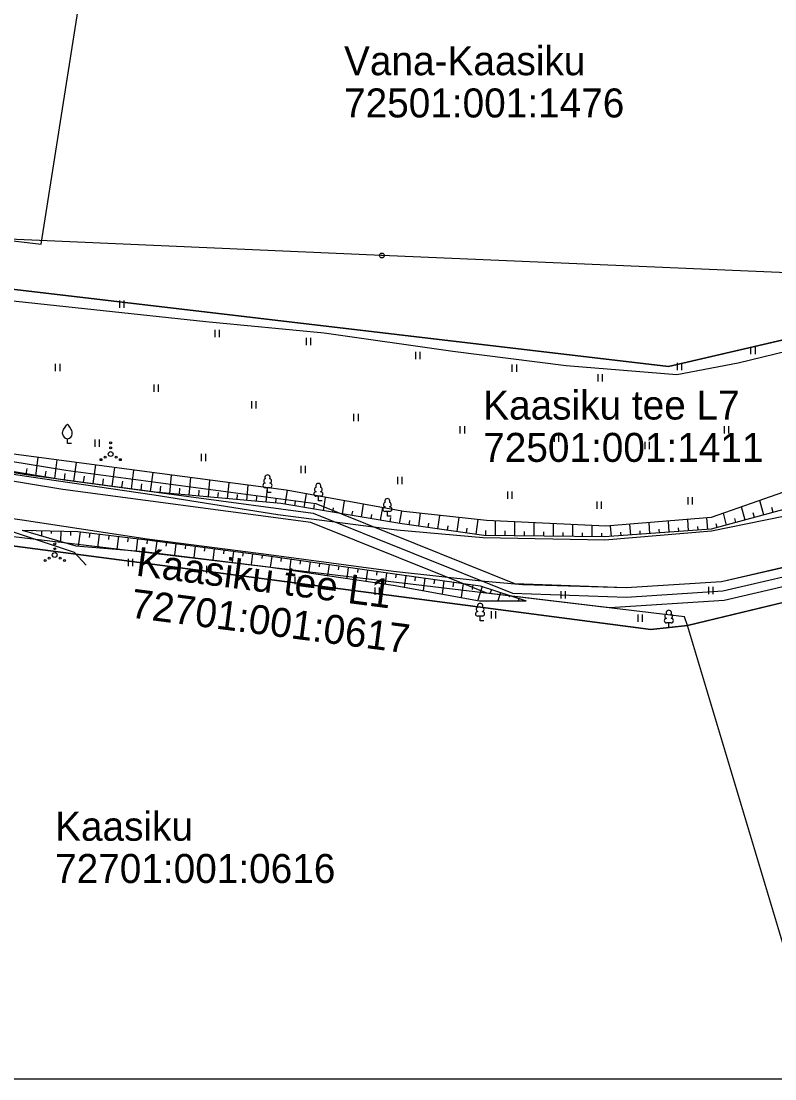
# Model space of a CAD drawing. Extents: x 532656 to 533339, y 6581345 to 6581629.
# Drawn here: x 533058.1 to 533136.1, y 6581421.7 to 6581531.1 of the extents above; entities that cross this region are included whole.
import ezdxf

# ---------------------------------------------------------------- set-up
doc = ezdxf.new("R2010")
doc.units = 0
for name, color, linetype in [('HALJASTUS', 7, 'Continuous'), ('KASUTUSALA', 7, 'Continuous'), ('MPKAABEL', 7, 'Continuous'), ('MPOHULIIN', 7, 'Continuous'), ('PIIR', 7, 'Continuous'), ('POST', 7, 'Continuous'), ('PR_SIDE', 7, 'Continuous'), ('PUU', 7, 'Continuous'), ('RELJEEF', 7, 'Continuous'), ('TEE', 7, 'Continuous'), ('VORMISTUS', 7, 'Continuous')]:
    doc.layers.add(name, color=color, linetype=linetype)

msp = doc.modelspace()

# ---------------------------------------------------------------- linework, layer by layer
at = {"layer": 'HALJASTUS'}
for p, q in [((533068.28, 6581502.21), (533068.28, 6581501.45)), ((533068.73, 6581502.21), (533068.73, 6581501.45)), ((533078.15, 6581499.17), (533078.15, 6581498.41)), ((533078.61, 6581499.17), (533078.61, 6581498.41)), ((533087.6, 6581498.33), (533087.6, 6581497.57)), ((533088.06, 6581498.33), (533088.06, 6581497.57)), ((533133.6, 6581497.4), (533133.6, 6581496.64)), ((533134.06, 6581497.4), (533134.06, 6581496.64)), ((533098.91, 6581496.89), (533098.91, 6581496.13)), ((533099.37, 6581496.89), (533099.37, 6581496.13)), ((533061.65, 6581495.63), (533061.65, 6581494.87)), ((533062.11, 6581495.63), (533062.11, 6581494.87)), ((533108.91, 6581495.58), (533108.91, 6581494.82)), ((533109.37, 6581495.58), (533109.37, 6581494.82)), ((533126.01, 6581495.75), (533126.01, 6581494.99)), ((533126.46, 6581495.75), (533126.46, 6581494.99)), ((533117.78, 6581494.57), (533117.78, 6581493.81)), ((533118.23, 6581494.57), (533118.23, 6581493.81)), ((533071.84, 6581493.49), (533071.84, 6581492.73)), ((533072.3, 6581493.49), (533072.3, 6581492.73)), ((533081.96, 6581491.79), (533081.96, 6581491.03)), ((533082.41, 6581491.79), (533082.41, 6581491.03)), ((533092.52, 6581490.46), (533092.52, 6581489.7)), ((533092.98, 6581490.46), (533092.98, 6581489.7)), ((533103.52, 6581489.21), (533103.52, 6581488.44)), ((533103.98, 6581489.21), (533103.98, 6581488.44)), ((533130.85, 6581489.21), (533130.85, 6581488.44)), ((533131.3, 6581489.21), (533131.3, 6581488.44)), ((533065.74, 6581487.83), (533065.74, 6581487.07)), ((533066.2, 6581487.83), (533066.2, 6581487.07)), ((533113.27, 6581488.32), (533113.27, 6581487.56)), ((533113.73, 6581488.32), (533113.73, 6581487.56)), ((533122.65, 6581487.58), (533122.65, 6581486.82)), ((533123.11, 6581487.58), (533123.11, 6581486.82)), ((533076.76, 6581486.35), (533076.76, 6581485.59)), ((533077.21, 6581486.35), (533077.21, 6581485.59)), ((533087.06, 6581485.09), (533087.06, 6581484.33)), ((533087.51, 6581485.09), (533087.51, 6581484.33)), ((533097.06, 6581483.95), (533097.06, 6581483.19)), ((533097.51, 6581483.95), (533097.51, 6581483.19)), ((533108.45, 6581482.43), (533108.45, 6581481.67)), ((533108.91, 6581482.43), (533108.91, 6581481.67)), ((533117.69, 6581481.41), (533117.69, 6581480.65)), ((533118.15, 6581481.41), (533118.15, 6581480.65)), ((533127.1, 6581481.84), (533127.1, 6581481.08)), ((533127.56, 6581481.84), (533127.56, 6581481.08)), ((533069.19, 6581475.46), (533069.19, 6581474.7)), ((533069.64, 6581475.46), (533069.64, 6581474.7)), ((533077.29, 6581474.74), (533077.29, 6581473.98)), ((533077.75, 6581474.74), (533077.75, 6581473.98)), ((533086.45, 6581473.6), (533086.45, 6581472.84)), ((533086.9, 6581473.6), (533086.9, 6581472.84)), ((533094.72, 6581472.5), (533094.72, 6581471.74)), ((533095.18, 6581472.5), (533095.18, 6581471.74)), ((533129.24, 6581472.59), (533129.24, 6581471.82)), ((533129.69, 6581472.59), (533129.69, 6581471.82)), ((533113.96, 6581472.12), (533113.96, 6581471.36)), ((533114.42, 6581472.12), (533114.42, 6581471.36)), ((533106.75, 6581470.05), (533106.75, 6581469.29)), ((533107.2, 6581470.05), (533107.2, 6581469.29)), ((533121.94, 6581469.71), (533121.94, 6581468.95)), ((533122.39, 6581469.71), (533122.39, 6581468.95))]:
    msp.add_line(p, q, dxfattribs=at)
msp.add_lwpolyline([(533032.97, 6581478.99), (533033.72, 6581480.95), (533045.3, 6581480.01), (533057.4, 6581478.22), (533063.59, 6581476.17), (533064.85, 6581474.81)], dxfattribs=at)
for centre, radius in [((533067.38, 6581487.46), 0.1), ((533067.38, 6581486.31), 0.25), ((533067.38, 6581486.96), 0.1), ((533066.38, 6581485.73), 0.1), ((533066.82, 6581485.98), 0.1), ((533067.95, 6581485.98), 0.1), ((533068.38, 6581485.73), 0.1), ((533061.59, 6581477.02), 0.1), ((533061.59, 6581476.52), 0.1), ((533061.02, 6581475.54), 0.1), ((533061.59, 6581475.87), 0.25), ((533062.15, 6581475.54), 0.1), ((533060.59, 6581475.29), 0.1), ((533062.59, 6581475.29), 0.1)]:
    msp.add_circle(centre, radius, dxfattribs=at)
at = {"layer": 'KASUTUSALA'}
for points in [[(533013.98, 6581493.3), (533015.9, 6581507.09), (533016.05, 6581508.19), (533018.04, 6581507.96), (533017.92, 6581507.09), (533016.06, 6581493.72), (533016.82, 6581492.43), (533018.77, 6581491.63), (533020.53, 6581491.21), (533026.48, 6581490.1), (533037.85, 6581488.72), (533062.74, 6581484.63), (533088.6, 6581481.18), (533109.16, 6581472.91), (533120.73, 6581472.5), (533130.59, 6581473.14), (533152.46, 6581478.24)], [(533152.98, 6581476.31), (533130.88, 6581471.16), (533119.05, 6581470.39), (533116.99, 6581470.63), (533106.31, 6581471.91), (533088.09, 6581479.24), (533062.44, 6581482.66), (533037.57, 6581486.74), (533026.18, 6581488.12), (533021.07, 6581489.07), (533020.13, 6581489.24), (533009.66, 6581490.74)]]:
    msp.add_lwpolyline(points, dxfattribs=at)
at = {"layer": 'MPKAABEL'}
msp.add_lwpolyline([(533187.88, 6581502.84), (533186.34, 6581502.82), (533179.65, 6581502.93), (533170.99, 6581502.81), (533161.86, 6581502.74), (533157.45, 6581501.85), (533146.33, 6581499.15), (533143.65, 6581498.48), (533132.32, 6581495.71), (533125.95, 6581494.5), (533114.52, 6581495.45), (533102.79, 6581496.92), (533089.47, 6581498.82), (533077.24, 6581500), (533065.63, 6581501.23), (533053.69, 6581502.51), (533042.29, 6581503.73), (533032.02, 6581504.88), (533032.28, 6581506.42), (533031.89, 6581506.81)], dxfattribs=at)
msp.add_lwpolyline([(533187.88, 6581502.84), (533186.34, 6581502.82), (533179.65, 6581502.93), (533170.99, 6581502.81), (533161.86, 6581502.74), (533157.45, 6581501.85), (533146.33, 6581499.15), (533143.65, 6581498.48), (533132.32, 6581495.71), (533125.95, 6581494.5), (533114.52, 6581495.45), (533102.79, 6581496.92), (533089.47, 6581498.82), (533077.24, 6581500), (533065.63, 6581501.23), (533053.69, 6581502.51), (533042.29, 6581503.73), (533032.02, 6581504.88), (533032.28, 6581506.42), (533031.89, 6581506.81)], dxfattribs=at)
at = {"layer": 'MPOHULIIN'}
msp.add_lwpolyline([(533275.32, 6581502.37), (533268.53, 6581499.28), (533228.29, 6581500.87), (533187.88, 6581502.84), (533141.43, 6581504.88), (533095.45, 6581506.85), (533050.54, 6581508.81), (533010.87, 6581510.54), (532997.7, 6581528.31)], dxfattribs=at)
at = {"layer": 'PIIR'}
for points in [[(532997.7, 6581558.35), (533016.96, 6581555.16), (533011.51, 6581513.79), (533060.19, 6581508.02), (533066.33, 6581546.98), (533091.13, 6581542.87), (533143.65, 6581562.67), (533173.8, 6581529.09), (533205.25, 6581513.98), (533125.12, 6581495.35), (532997.7, 6581510.35)], [(532997.7, 6581510.35), (533125.12, 6581495.35), (533271.76, 6581529.44), (533289.68, 6581507.68), (533127.07, 6581468.59), (533126.77, 6581469.47), (532997.7, 6581484.84)], [(533141.13, 6581421.68), (533127.07, 6581468.59), (533267.77, 6581502.5), (533292.38, 6581484.15), (533309.59, 6581464.94)], [(532997.7, 6581483.86), (533035.33, 6581479.69), (533123.26, 6581468.15), (533127.07, 6581468.59), (533126.77, 6581469.47), (532997.7, 6581484.84)], [(533141.13, 6581421.68), (533127.07, 6581468.59), (533123.26, 6581468.15), (533035.33, 6581479.69), (533032.98, 6581458.23), (533019.26, 6581430.2), (532997.7, 6581433.84)]]:
    msp.add_lwpolyline(points, dxfattribs=at)
msp.add_lwpolyline([(533066.33, 6581546.98), (533016.96, 6581555.16), (533011.51, 6581513.79), (533060.19, 6581508.02)], close=True, dxfattribs=at)
at = {"layer": 'POST'}
for radius in [0.25, 0.0234]:
    msp.add_circle((533095.45, 6581506.85), radius, dxfattribs=at)
at = {"layer": 'PR_SIDE'}
msp.add_lwpolyline([(533009.76, 6581491.73), (533020.32, 6581490.23), (533026.33, 6581489.11), (533037.71, 6581487.73), (533062.59, 6581483.65), (533088.35, 6581480.21), (533108.95, 6581471.92), (533120.75, 6581471.5), (533130.73, 6581472.15), (533152.72, 6581477.27), (533179.95, 6581485.59), (533320.87, 6581524.82)], dxfattribs=at)
at = {"layer": 'PUU'}
for p, q in [((533062.91, 6581487.4), (533062.91, 6581487.9)), ((533063.31, 6581487.4), (533062.91, 6581487.4)), ((533083.86, 6581482.83), (533083.38, 6581482.83)), ((533083.62, 6581482.35), (533083.62, 6581482.83)), ((533084, 6581482.35), (533083.62, 6581482.35)), ((533089.11, 6581481.94), (533088.63, 6581481.94)), ((533088.87, 6581481.47), (533088.87, 6581481.94)), ((533089.25, 6581481.47), (533088.87, 6581481.47)), ((533096.25, 6581480.38), (533095.77, 6581480.38)), ((533096.01, 6581479.9), (533096.01, 6581480.38)), ((533096.39, 6581479.9), (533096.01, 6581479.9)), ((533105.85, 6581469.54), (533105.37, 6581469.54)), ((533105.61, 6581469.07), (533105.61, 6581469.54)), ((533105.99, 6581469.07), (533105.61, 6581469.07)), ((533125.37, 6581468.84), (533124.89, 6581468.84)), ((533125.13, 6581468.36), (533125.13, 6581468.84)), ((533125.51, 6581468.36), (533125.13, 6581468.36))]:
    msp.add_line(p, q, dxfattribs=at)
for points in [[(533062.41, 6581488.4), (533062.41, 6581488.55), (533062.42, 6581488.61), (533062.45, 6581488.74), (533062.51, 6581488.86), (533062.66, 6581489.1), (533062.82, 6581489.3), (533062.91, 6581489.4)], [(533063.41, 6581488.4), (533063.41, 6581488.55), (533063.4, 6581488.61), (533063.36, 6581488.74), (533063.3, 6581488.86), (533063.16, 6581489.1), (533063, 6581489.3), (533062.91, 6581489.4)]]:
    msp.add_lwpolyline(points, dxfattribs=at)
for centre, radius, start, end in [((533062.91, 6581488.4), 0.5, 180, 0), ((533083.38, 6581483.07), 0.238, 90.0016, 269.3953), ((533083.45, 6581483.53), 0.233, 109.0217, 253.1415), ((533083.62, 6581483.87), 0.277, 332.5799, 207.4201), ((533083.79, 6581483.53), 0.233, 286.8508, 70.9859), ((533083.85, 6581483.07), 0.238, 270.6047, 89.9984), ((533088.87, 6581482.99), 0.277, 332.5799, 207.4201), ((533088.63, 6581482.18), 0.238, 90.0016, 269.3953), ((533088.7, 6581482.64), 0.233, 109.0217, 253.1415), ((533089.04, 6581482.64), 0.233, 286.8508, 70.9859), ((533089.1, 6581482.18), 0.238, 270.6047, 89.9984), ((533095.84, 6581481.07), 0.233, 109.0217, 253.1415), ((533096.01, 6581481.42), 0.277, 332.5799, 207.4201), ((533096.18, 6581481.07), 0.233, 286.8508, 70.9859), ((533095.77, 6581480.61), 0.238, 90.0016, 269.3953), ((533096.25, 6581480.61), 0.238, 270.6047, 89.9984), ((533105.37, 6581469.78), 0.238, 90.0016, 269.3953), ((533105.44, 6581470.24), 0.233, 109.0217, 253.1415), ((533105.61, 6581470.59), 0.277, 332.5799, 207.4201), ((533105.78, 6581470.24), 0.233, 286.8508, 70.9859), ((533105.84, 6581469.78), 0.238, 270.6047, 89.9984), ((533125.13, 6581469.88), 0.277, 332.5799, 207.4201), ((533124.9, 6581469.08), 0.238, 90.0016, 269.3953), ((533124.96, 6581469.54), 0.233, 109.0217, 253.1415), ((533125.3, 6581469.54), 0.233, 286.8508, 70.9859), ((533125.37, 6581469.08), 0.238, 270.6047, 89.9984)]:
    msp.add_arc(centre, radius, start, end, dxfattribs=at)
at = {"layer": 'RELJEEF'}
for p, q in [((533059.62, 6581484.05), (533059.88, 6581485.97)), ((533061.6, 6581483.78), (533061.86, 6581485.7)), ((533063.58, 6581483.51), (533063.84, 6581485.44)), ((533058.63, 6581484.19), (533058.73, 6581484.82)), ((533060.61, 6581483.91), (533060.7, 6581484.55)), ((533062.59, 6581483.65), (533062.68, 6581484.29)), ((533065.57, 6581483.25), (533065.83, 6581485.18)), ((533067.55, 6581482.98), (533067.81, 6581484.92)), ((533069.53, 6581482.71), (533069.79, 6581484.66)), ((533071.51, 6581482.45), (533071.77, 6581484.39)), ((533064.57, 6581483.38), (533064.66, 6581484.02)), ((533066.56, 6581483.11), (533066.64, 6581483.76)), ((533068.54, 6581482.85), (533068.63, 6581483.49)), ((533070.52, 6581482.58), (533070.61, 6581483.23)), ((533073.5, 6581482.24), (533073.68, 6581484.14)), ((533075.49, 6581482.06), (533075.66, 6581483.88)), ((533077.49, 6581481.88), (533077.64, 6581483.61)), ((533079.48, 6581481.7), (533079.63, 6581483.35)), ((533072.51, 6581482.34), (533072.57, 6581482.98)), ((533074.5, 6581482.15), (533074.55, 6581482.77)), ((533076.49, 6581481.97), (533076.54, 6581482.56)), ((533078.48, 6581481.79), (533078.53, 6581482.35)), ((533080.47, 6581481.6), (533080.52, 6581482.14)), ((533081.47, 6581481.51), (533081.61, 6581483.08)), ((533083.46, 6581481.33), (533083.6, 6581482.81)), ((533085.45, 6581481.11), (533085.68, 6581482.53)), ((533087.42, 6581480.78), (533087.65, 6581482.18)), ((533082.46, 6581481.42), (533082.51, 6581481.93)), ((533084.46, 6581481.24), (533084.5, 6581481.72)), ((533086.43, 6581480.95), (533086.51, 6581481.42)), ((533088.41, 6581480.62), (533088.48, 6581481.08)), ((533089.39, 6581480.45), (533089.62, 6581481.82)), ((533091.36, 6581480.12), (533091.59, 6581481.47)), ((533093.34, 6581479.79), (533093.56, 6581481.12)), ((533134.97, 6581480), (533134.56, 6581481.52)), ((533090.38, 6581480.29), (533090.45, 6581480.74)), ((533092.35, 6581479.95), (533092.43, 6581480.4)), ((533094.32, 6581479.62), (533094.4, 6581480.06)), ((533095.31, 6581479.46), (533095.53, 6581480.77)), ((533097.28, 6581479.13), (533097.5, 6581480.41)), ((533099.26, 6581478.85), (533099.45, 6581480.18)), ((533101.24, 6581478.57), (533101.44, 6581479.96)), ((533131.11, 6581478.96), (533130.78, 6581480.18)), ((533133.04, 6581479.48), (533132.67, 6581480.85)), ((533134, 6581479.74), (533133.87, 6581480.22)), ((533135.94, 6581480.26), (533135.79, 6581480.79)), ((533096.3, 6581479.29), (533096.37, 6581479.73)), ((533098.27, 6581478.99), (533098.33, 6581479.42)), ((533100.25, 6581478.71), (533100.32, 6581479.16)), ((533102.23, 6581478.43), (533102.3, 6581478.9)), ((533103.22, 6581478.29), (533103.43, 6581479.75)), ((533105.2, 6581478.01), (533105.42, 6581479.53)), ((533107.19, 6581477.88), (533107.21, 6581479.39)), ((533109.19, 6581477.85), (533109.21, 6581479.29)), ((533111.19, 6581477.83), (533111.21, 6581479.2)), ((533113.19, 6581477.8), (533113.21, 6581479.1)), ((533115.19, 6581477.78), (533115.21, 6581479.01)), ((533117.19, 6581477.75), (533117.21, 6581478.92)), ((533119.19, 6581477.78), (533119.11, 6581478.89)), ((533121.19, 6581477.93), (533121.11, 6581479.05)), ((533123.18, 6581478.07), (533123.1, 6581479.22)), ((533125.18, 6581478.22), (533125.09, 6581479.38)), ((533127.17, 6581478.36), (533127.09, 6581479.54)), ((533128.17, 6581478.43), (533128.14, 6581478.83)), ((533129.17, 6581478.5), (533129.08, 6581479.71)), ((533130.14, 6581478.7), (533130.04, 6581479.08)), ((533132.07, 6581479.22), (533131.96, 6581479.65)), ((533059.22, 6581478.42), (533059.22, 6581478.33)), ((533060.22, 6581478.4), (533060.21, 6581477.86)), ((533061.22, 6581478.37), (533061.21, 6581478.1)), ((533062.22, 6581478.35), (533062.19, 6581477.27)), ((533063.22, 6581478.33), (533063.21, 6581477.88)), ((533064.22, 6581478.28), (533064.03, 6581476.78)), ((533065.21, 6581478.16), (533065.15, 6581477.67)), ((533066.2, 6581478.04), (533066.03, 6581476.62)), ((533067.19, 6581477.92), (533067.14, 6581477.46)), ((533068.19, 6581477.8), (533068.02, 6581476.46)), ((533069.18, 6581477.67), (533069.13, 6581477.24)), ((533104.21, 6581478.15), (533104.28, 6581478.64)), ((533106.2, 6581477.89), (533106.2, 6581478.41)), ((533108.19, 6581477.87), (533108.2, 6581478.36)), ((533110.19, 6581477.84), (533110.2, 6581478.31)), ((533112.19, 6581477.81), (533112.2, 6581478.26)), ((533114.19, 6581477.79), (533114.2, 6581478.21)), ((533116.19, 6581477.76), (533116.2, 6581478.16)), ((533118.19, 6581477.74), (533118.2, 6581478.11)), ((533120.19, 6581477.86), (533120.16, 6581478.23)), ((533122.18, 6581478), (533122.16, 6581478.38)), ((533124.18, 6581478.14), (533124.15, 6581478.53)), ((533126.17, 6581478.29), (533126.15, 6581478.68)), ((533070.17, 6581477.55), (533070.02, 6581476.29)), ((533071.17, 6581477.43), (533071.11, 6581477.02)), ((533072.16, 6581477.3), (533072, 6581476.08)), ((533073.15, 6581477.17), (533073.09, 6581476.77)), ((533074.14, 6581477.04), (533073.98, 6581475.84)), ((533075.13, 6581476.91), (533075.08, 6581476.51)), ((533076.12, 6581476.78), (533075.97, 6581475.6)), ((533077.11, 6581476.64), (533077.06, 6581476.25)), ((533078.1, 6581476.51), (533077.95, 6581475.35)), ((533079.1, 6581476.38), (533079.05, 6581476)), ((533080.09, 6581476.25), (533079.94, 6581475.11)), ((533081.08, 6581476.12), (533081.03, 6581475.74)), ((533082.07, 6581475.99), (533081.92, 6581474.87)), ((533083.06, 6581475.86), (533083.01, 6581475.49)), ((533084.05, 6581475.72), (533083.89, 6581474.62)), ((533085.04, 6581475.58), (533084.99, 6581475.21)), ((533086.03, 6581475.44), (533085.87, 6581474.33)), ((533087.02, 6581475.3), (533086.97, 6581474.92)), ((533088.01, 6581475.16), (533087.85, 6581474.03)), ((533089, 6581475.01), (533088.95, 6581474.64)), ((533089.99, 6581474.87), (533089.83, 6581473.74)), ((533090.98, 6581474.73), (533090.93, 6581474.35)), ((533091.97, 6581474.59), (533091.81, 6581473.45)), ((533092.96, 6581474.45), (533092.91, 6581474.07)), ((533093.95, 6581474.31), (533093.79, 6581473.16)), ((533094.94, 6581474.17), (533094.89, 6581473.78)), ((533095.93, 6581474.02), (533095.77, 6581472.87)), ((533096.92, 6581473.88), (533096.87, 6581473.49)), ((533097.91, 6581473.75), (533097.74, 6581472.54)), ((533098.9, 6581473.61), (533098.84, 6581473.19)), ((533099.89, 6581473.47), (533099.71, 6581472.19)), ((533100.88, 6581473.33), (533100.82, 6581472.89)), ((533101.87, 6581473.19), (533101.68, 6581471.84)), ((533102.86, 6581473.05), (533102.8, 6581472.59)), ((533103.85, 6581472.91), (533103.65, 6581471.49)), ((533104.84, 6581472.78), (533104.78, 6581472.29)), ((533105.83, 6581472.6), (533105.37, 6581471.18)), ((533106.78, 6581472.3), (533106.66, 6581471.91)), ((533107.73, 6581471.99), (533107.46, 6581471.14)), ((533108.68, 6581471.69), (533108.63, 6581471.51)), ((533109.64, 6581471.38), (533109.56, 6581471.14))]:
    msp.add_line(p, q, dxfattribs=at)
for points in [[(533281.18, 6581520.42), (533276.05, 6581519.36), (533263.6, 6581516.53), (533251.65, 6581514.59), (533239.04, 6581512.21), (533226.47, 6581508.91), (533214.68, 6581505.26), (533201.89, 6581501.28), (533176.76, 6581494.49), (533164.99, 6581490.87), (533152.25, 6581486.88), (533140.46, 6581483.59), (533129.53, 6581479.74), (533118.62, 6581478.85), (533106.28, 6581479.43), (533097.7, 6581480.38), (533085.54, 6581482.56), (533072.44, 6581484.31), (533059.43, 6581486.03), (533046.01, 6581487.79), (533038.24, 6581488.57), (533036.77, 6581489.1), (533035.51, 6581491.06)], [(533281.56, 6581519.42), (533276.26, 6581518.13), (533263.82, 6581515.5), (533251.69, 6581513.67), (533239.15, 6581511.33), (533226.72, 6581507.82), (533214.83, 6581504.27), (533202.1, 6581500.22), (533189.78, 6581497.01), (533177.29, 6581493.01), (533165.35, 6581489.17), (533152.46, 6581485.11), (533140.73, 6581481.56), (533129.52, 6581478.53), (533118.47, 6581477.73), (533106, 6581477.89), (533097.29, 6581479.13), (533084.98, 6581481.19), (533071.98, 6581482.38), (533058.89, 6581484.14), (533045.84, 6581486.18), (533037.75, 6581487.16), (533036.17, 6581488.64), (533035.51, 6581491.06)], [(533058.22, 6581478.45), (533063.98, 6581478.31), (533071.14, 6581477.44), (533083.7, 6581475.77), (533096.77, 6581473.91), (533105.62, 6581472.67), (533110.39, 6581471.14)], [(533058.22, 6581478.45), (533063.78, 6581476.8), (533070.8, 6581476.23), (533083.45, 6581474.68), (533096.61, 6581472.74), (533105.56, 6581471.14), (533110.39, 6581471.14)]]:
    msp.add_lwpolyline(points, dxfattribs=at)
at = {"layer": 'TEE'}
for points in [[(533140.89, 6581480.63), (533129.55, 6581478.32), (533118.51, 6581477.4), (533105.92, 6581477.64), (533096.99, 6581478.44), (533084.67, 6581480.03), (533071.89, 6581482.05), (533058.9, 6581483.97), (533045.77, 6581485.95), (533037.63, 6581486.92), (533036.04, 6581488.52), (533035.42, 6581490.45), (533035.42, 6581492.71), (533036.48, 6581499.41), (533037.46, 6581506.01)], [(533011.56, 6581485.02), (533021.87, 6581484.15), (533034.21, 6581482.84), (533045.47, 6581481.3), (533058.22, 6581479.5), (533071.17, 6581477.55), (533083.74, 6581475.92), (533096.64, 6581474.2), (533105.72, 6581473.21), (533110.01, 6581472.82), (533120.73, 6581472.5), (533130.59, 6581473.14), (533142.41, 6581475.8)]]:
    msp.add_lwpolyline(points, dxfattribs=at)
at = {"layer": 'VORMISTUS'}
msp.add_lwpolyline([(533309.59, 6581421.68), (533309.59, 6581605.42), (532997.7, 6581605.42), (532997.7, 6581421.68)], close=True, dxfattribs=at)
msp.add_lwpolyline([(532997.7, 6581421.68), (533309.59, 6581421.68)], dxfattribs=at)

# ---------------------------------------------------------------- texts
at = {"layer": 'PIIR'}
for s, p in [('Vana-Kaasiku', (533091.53, 6581525.5)), ('72501:001:1476', (533091.53, 6581521.13)), ('Kaasiku tee L7', (533105.93, 6581489.88)), ('72501:001:1411', (533105.93, 6581485.5)), ('Kaasiku', (533061.63, 6581446.31)), ('72701:001:0616', (533061.63, 6581441.94))]:
    msp.add_text(s, height=3, dxfattribs=at).set_placement(p)
for s, p in [('Kaasiku tee L1', (533069.91, 6581473.75)), ('72701:001:0617', (533069.34, 6581469.41))]:
    msp.add_text(s, height=3, rotation=352.6147, dxfattribs=at).set_placement(p)

doc.saveas('drawing.dxf')
